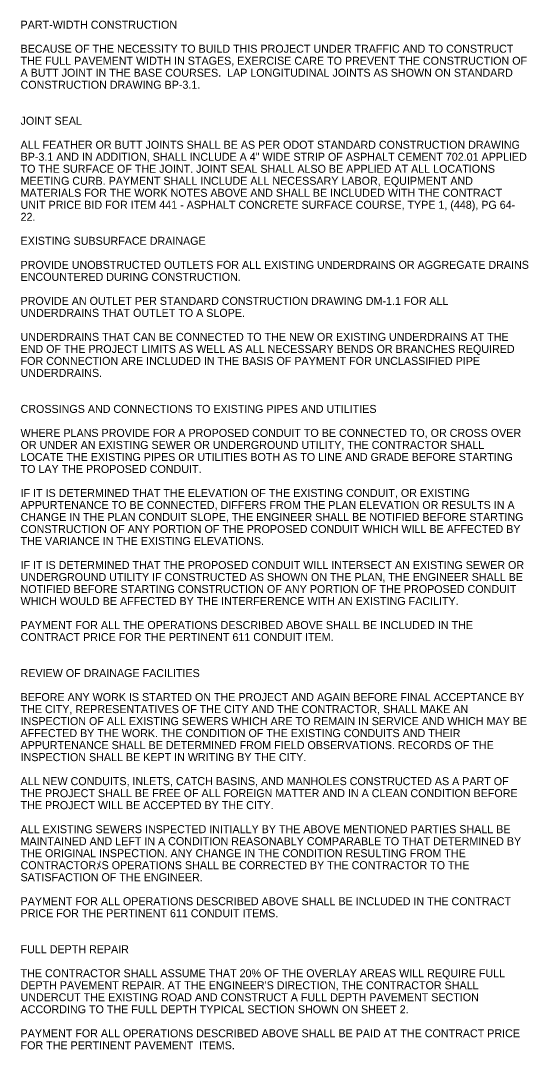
# Model space of a CAD drawing. Extents: x -8.5 to 44.5, y -22.3 to 22.
# Drawn here: x 35.59 to 44.46, y 3.01 to 21 of the extents above; entities that cross this region are included whole.
import ezdxf

# ---------------------------------------------------------------- set-up
doc = ezdxf.new("R2010")
doc.units = 0
doc.layers.add('SV_X_Random_Point', color=7, linetype='Continuous')

msp = doc.modelspace()

# ---------------------------------------------------------------- texts
at = {"layer": 'SV_X_Random_Point'}
for s, p in [('PART-WIDTH CONSTRUCTION', (35.587, 20.86)), ('BECAUSE OF THE NECESSITY TO BUILD THIS PROJECT UNDER TRAFFIC AND TO CONSTRUCT ', (35.587, 20.44)), ('THE FULL PAVEMENT WIDTH IN STAGES, EXERCISE CARE TO PREVENT THE CONSTRUCTION OF ', (35.587, 20.23)), ('A BUTT JOINT IN THE BASE COURSES.  LAP LONGITUDINAL JOINTS AS SHOWN ON STANDARD ', (35.587, 20.02)), ('CONSTRUCTION DRAWING BP-3.1.', (35.587, 19.81)), ('JOINT SEAL', (35.587, 19.18)), ('ALL FEATHER OR BUTT JOINTS SHALL BE AS PER ODOT STANDARD CONSTRUCTION DRAWING ', (35.587, 18.76)), ('BP-3.1 AND IN ADDITION, SHALL INCLUDE A 4" WIDE STRIP OF ASPHALT CEMENT 702.01 APPLIED ', (35.587, 18.55)), ('TO THE SURFACE OF THE JOINT. JOINT SEAL SHALL ALSO BE APPLIED AT ALL LOCATIONS ', (35.587, 18.34)), ('MEETING CURB. PAYMENT SHALL INCLUDE ALL NECESSARY LABOR, EQUIPMENT AND ', (35.587, 18.13)), ('MATERIALS FOR THE WORK NOTES ABOVE AND SHALL BE INCLUDED WITH THE CONTRACT ', (35.587, 17.92)), ('UNIT PRICE BID FOR ITEM 441 - ASPHALT CONCRETE SURFACE COURSE, TYPE 1, (448), PG 64-', (35.587, 17.71)), ('22.', (35.587, 17.5)), ('EXISTING SUBSURFACE DRAINAGE', (35.587, 17.08)), ('PROVIDE UNOBSTRUCTED OUTLETS FOR ALL EXISTING UNDERDRAINS OR AGGREGATE DRAINS ', (35.587, 16.66)), ('ENCOUNTERED DURING CONSTRUCTION.', (35.587, 16.45)), ('PROVIDE AN OUTLET PER STANDARD CONSTRUCTION DRAWING DM-1.1 FOR ALL ', (35.587, 16.03)), ('UNDERDRAINS THAT OUTLET TO A SLOPE.', (35.587, 15.82)), ('UNDERDRAINS THAT CAN BE CONNECTED TO THE NEW OR EXISTING UNDERDRAINS AT THE ', (35.587, 15.4)), ('END OF THE PROJECT LIMITS AS WELL AS ALL NECESSARY BENDS OR BRANCHES REQUIRED ', (35.587, 15.19)), ('FOR CONNECTION ARE INCLUDED IN THE BASIS OF PAYMENT FOR UNCLASSIFIED PIPE ', (35.587, 14.98)), ('UNDERDRAINS.', (35.587, 14.77)), ('CROSSINGS AND CONNECTIONS TO EXISTING PIPES AND UTILITIES', (35.587, 14.14)), ('WHERE PLANS PROVIDE FOR A PROPOSED CONDUIT TO BE CONNECTED TO, OR CROSS OVER ', (35.587, 13.72)), ('OR UNDER AN EXISTING SEWER OR UNDERGROUND UTILITY, THE CONTRACTOR SHALL ', (35.587, 13.51)), ('LOCATE THE EXISTING PIPES OR UTILITIES BOTH AS TO LINE AND GRADE BEFORE STARTING ', (35.587, 13.3)), ('TO LAY THE PROPOSED CONDUIT.', (35.587, 13.09)), ('IF IT IS DETERMINED THAT THE ELEVATION OF THE EXISTING CONDUIT, OR EXISTING ', (35.587, 12.67)), ('APPURTENANCE TO BE CONNECTED, DIFFERS FROM THE PLAN ELEVATION OR RESULTS IN A ', (35.587, 12.46)), ('CHANGE IN THE PLAN CONDUIT SLOPE, THE ENGINEER SHALL BE NOTIFIED BEFORE STARTING ', (35.587, 12.25)), ('CONSTRUCTION OF ANY PORTION OF THE PROPOSED CONDUIT WHICH WILL BE AFFECTED BY ', (35.587, 12.04)), ('THE VARIANCE IN THE EXISTING ELEVATIONS.', (35.587, 11.83)), ('IF IT IS DETERMINED THAT THE PROPOSED CONDUIT WILL INTERSECT AN EXISTING SEWER OR ', (35.587, 11.41)), ('UNDERGROUND UTILITY IF CONSTRUCTED AS SHOWN ON THE PLAN, THE ENGINEER SHALL BE ', (35.587, 11.2)), ('NOTIFIED BEFORE STARTING CONSTRUCTION OF ANY PORTION OF THE PROPOSED CONDUIT ', (35.587, 10.99)), ('WHICH WOULD BE AFFECTED BY THE INTERFERENCE WITH AN EXISTING FACILITY.', (35.587, 10.78)), ('PAYMENT FOR ALL THE OPERATIONS DESCRIBED ABOVE SHALL BE INCLUDED IN THE ', (35.587, 10.36)), ('CONTRACT PRICE FOR THE PERTINENT 611 CONDUIT ITEM.', (35.587, 10.15)), ('REVIEW OF DRAINAGE FACILITIES', (35.587, 9.52)), ('BEFORE ANY WORK IS STARTED ON THE PROJECT AND AGAIN BEFORE FINAL ACCEPTANCE BY ', (35.587, 9.1)), ('THE CITY, REPRESENTATIVES OF THE CITY AND THE CONTRACTOR, SHALL MAKE AN ', (35.587, 8.89)), ('INSPECTION OF ALL EXISTING SEWERS WHICH ARE TO REMAIN IN SERVICE AND WHICH MAY BE ', (35.587, 8.68)), ('AFFECTED BY THE WORK. THE CONDITION OF THE EXISTING CONDUITS AND THEIR ', (35.587, 8.47)), ('APPURTENANCE SHALL BE DETERMINED FROM FIELD OBSERVATIONS. RECORDS OF THE ', (35.587, 8.26)), ('INSPECTION SHALL BE KEPT IN WRITING BY THE CITY.', (35.587, 8.05)), ('ALL NEW CONDUITS, INLETS, CATCH BASINS, AND MANHOLES CONSTRUCTED AS A PART OF ', (35.587, 7.63)), ('THE PROJECT SHALL BE FREE OF ALL FOREIGN MATTER AND IN A CLEAN CONDITION BEFORE ', (35.587, 7.42)), ('THE PROJECT WILL BE ACCEPTED BY THE CITY.', (35.587, 7.21)), ('ALL EXISTING SEWERS INSPECTED INITIALLY BY THE ABOVE MENTIONED PARTIES SHALL BE ', (35.587, 6.79)), ('MAINTAINED AND LEFT IN A CONDITION REASONABLY COMPARABLE TO THAT DETERMINED BY ', (35.587, 6.58)), ('THE ORIGINAL INSPECTION. ANY CHANGE IN THE CONDITION RESULTING FROM THE ', (35.587, 6.37)), ('CONTRACTORﾒS OPERATIONS SHALL BE CORRECTED BY THE CONTRACTOR TO THE ', (35.587, 6.16)), ('SATISFACTION OF THE ENGINEER.', (35.587, 5.95)), ('PAYMENT FOR ALL OPERATIONS DESCRIBED ABOVE SHALL BE INCLUDED IN THE CONTRACT ', (35.587, 5.53)), ('PRICE FOR THE PERTINENT 611 CONDUIT ITEMS.', (35.587, 5.32)), ('FULL DEPTH REPAIR', (35.587, 4.69)), ('THE CONTRACTOR SHALL ASSUME THAT 20% OF THE OVERLAY AREAS WILL REQUIRE FULL ', (35.587, 4.27)), ("DEPTH PAVEMENT REPAIR. AT THE ENGINEER'S DIRECTION, THE CONTRACTOR SHALL ", (35.587, 4.06)), ('UNDERCUT THE EXISTING ROAD AND CONSTRUCT A FULL DEPTH PAVEMENT SECTION ', (35.587, 3.85)), ('ACCORDING TO THE FULL DEPTH TYPICAL SECTION SHOWN ON SHEET 2.', (35.587, 3.64)), ('PAYMENT FOR ALL OPERATIONS DESCRIBED ABOVE SHALL BE PAID AT THE CONTRACT PRICE ', (35.587, 3.22)), ('FOR THE PERTINENT PAVEMENT  ITEMS.', (35.587, 3.01))]:
    msp.add_text(s, height=0.14, dxfattribs=at).set_placement(p)

doc.saveas('drawing.dxf')
